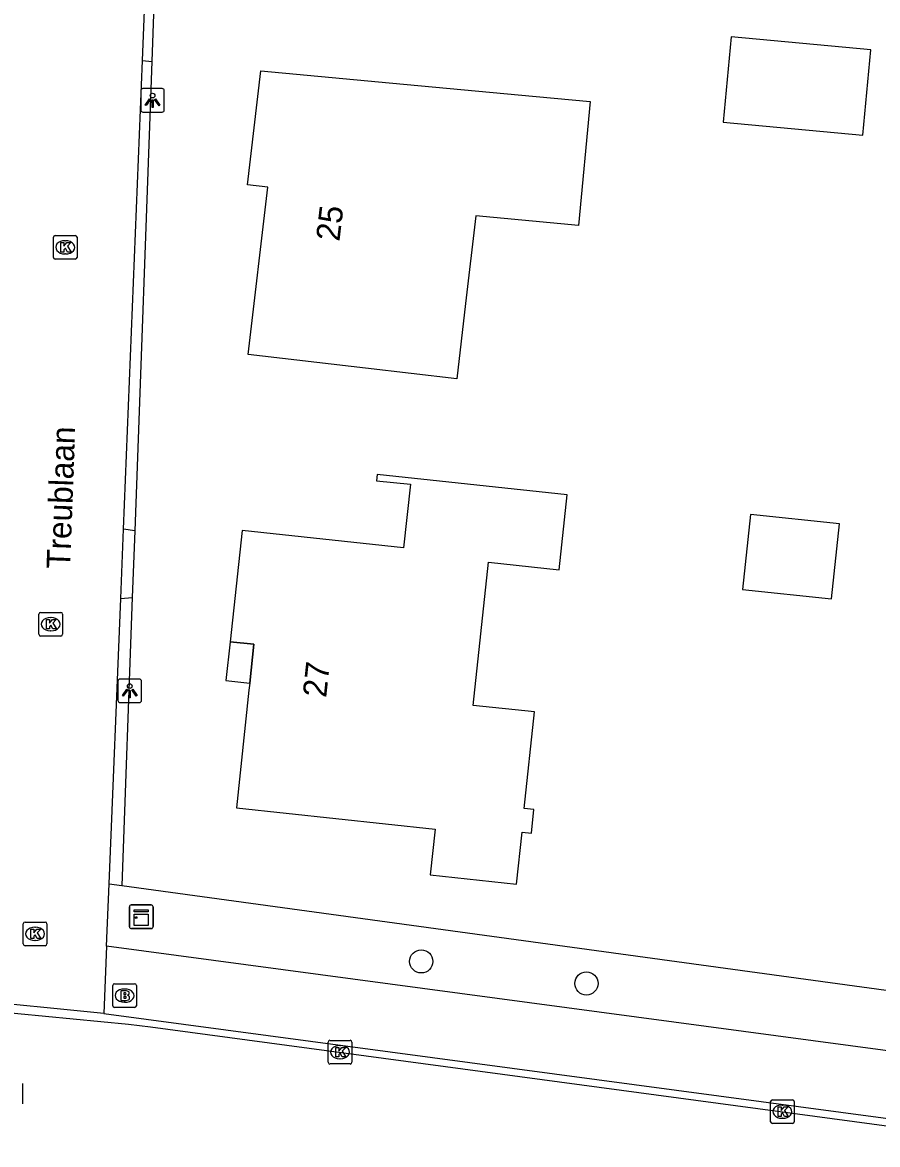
# Model space of a CAD drawing. Extents: x 162157 to 163165, y 378998 to 380775.
# Drawn here: x 162453.3 to 162489.44, y 380403.58 to 380451.03 of the extents above; entities that cross this region are included whole.
import ezdxf

# ---------------------------------------------------------------- set-up
doc = ezdxf.new("R2010")
doc.units = 0
for name, color, linetype in [('IMGEO_Berm_groen', 7, 'Continuous'), ('IMGEO_Boom', 7, 'Continuous'), ('IMGEO_Brandkraan', 7, 'Continuous'), ('IMGEO_Groenvoorziening', 7, 'Continuous'), ('IMGEO_Hek', 7, 'Continuous'), ('IMGEO_Kast', 7, 'Continuous'), ('IMGEO_Kolk', 7, 'Continuous'), ('IMGEO_Lichtpunt', 7, 'Continuous'), ('IMGEO_Openbare_ruimte_label', 7, 'Continuous'), ('IMGEO_Pand', 7, 'Continuous'), ('IMGEO_Pand_nummerreeks', 7, 'Continuous'), ('IMGEO_Pand_overbouw', 7, 'Continuous'), ('IMGEO_Rijbaan_lokaal_gesloten', 7, 'Continuous'), ('IMGEO_Rijbaan_lokaal_open', 7, 'Continuous'), ('IMGEO_Rioolput', 7, 'Continuous'), ('IMGEO_Voetpad_open', 7, 'Continuous')]:
    doc.layers.add(name, color=color, linetype=linetype)

msp = doc.modelspace()

# ---------------------------------------------------------------- linework, layer by layer
at = {"layer": 'IMGEO_Berm_groen'}
msp.add_lwpolyline([(162516.59, 380403.964), (162456.855, 380411.97)], dxfattribs=at)
at = {"layer": 'IMGEO_Boom'}
for centre in [(162470.152, 380411.323), (162477.137, 380410.39)]:
    msp.add_circle(centre, 0.489, dxfattribs=at)
at = {"layer": 'IMGEO_Brandkraan'}
for p, q in [((162457.11, 380409.451), (162457.11, 380410.303)), ((162457.185, 380410.377), (162458.037, 380410.377)), ((162457.598, 380410.157), (162457.623, 380410.157)), ((162458.111, 380410.303), (162458.111, 380409.451)), ((162458.037, 380409.377), (162457.185, 380409.377)), ((162457.621, 380409.597), (162457.596, 380409.597))]:
    msp.add_line(p, q, dxfattribs=at)
for points in [[(162457.11, 380409.451), (162457.11, 380410.303)], [(162457.185, 380410.377), (162458.037, 380410.377)], [(162458.111, 380410.303), (162458.111, 380409.451)], [(162457.458, 380410.077), (162457.458, 380409.677), (162457.671, 380409.677)], [(162457.689, 380410.077), (162457.458, 380410.077)], [(162457.637, 380409.996), (162457.583, 380409.996), (162457.583, 380409.92)], [(162457.583, 380409.92), (162457.636, 380409.92)], [(162457.645, 380409.844), (162457.583, 380409.844), (162457.583, 380409.763)], [(162457.583, 380409.763), (162457.645, 380409.763)], [(162458.037, 380409.377), (162457.185, 380409.377)]]:
    msp.add_lwpolyline(points, dxfattribs=at)
for centre, radius, start, end in [((162457.187, 380410.301), 0.0765, 91.552, 178.448), ((162457.187, 380410.301), 0.0765, 91.552, 178.448), ((162458.035, 380410.301), 0.0765, 1.552, 88.448), ((162458.035, 380410.301), 0.0765, 1.552, 88.448), ((162457.638, 380409.958), 0.0379, 267.8285, 90.9355), ((162457.646, 380409.803), 0.0404, 269.8759, 90.5077), ((162457.677, 380409.928), 0.251, 268.6676, 293.5347), ((162457.693, 380409.932), 0.145, 59.4692, 91.5367), ((162457.718, 380409.979), 0.0922, 285.5137, 58.1501), ((162457.723, 380409.787), 0.105, 301.3115, 78.989), ((162457.187, 380409.453), 0.0765, 181.552, 268.448), ((162457.187, 380409.453), 0.0765, 181.552, 268.448), ((162458.035, 380409.453), 0.0765, 271.552, 358.448), ((162458.035, 380409.453), 0.0765, 271.552, 358.448)]:
    msp.add_arc(centre, radius, start, end, dxfattribs=at)
for centre, major_axis, ratio, start_param, end_param in [((162457.597, 380409.877), (-0.387, 0.002), 0.722429, 4.712389, 7.853982), ((162457.622, 380409.877), (-0.39, 0.002), 0.717154, 1.570796, 4.712389)]:
    msp.add_ellipse(centre, major_axis=major_axis, ratio=ratio, start_param=start_param, end_param=end_param, dxfattribs=at)
at = {"layer": 'IMGEO_Groenvoorziening'}
msp.add_lwpolyline([(162457.497, 380414.534), (162500, 380408.709), (162516.524, 380406.414)], dxfattribs=at)
at = {"layer": 'IMGEO_Hek'}
msp.add_lwpolyline([(162457.497, 380414.534), (162500, 380408.709), (162516.524, 380406.414)], dxfattribs=at)
at = {"layer": 'IMGEO_Kast'}
for p, q in [((162457.818, 380412.786), (162457.818, 380413.627)), ((162457.818, 380413.627), (162457.818, 380412.786)), ((162457.893, 380413.711), (162458.734, 380413.711)), ((162458.734, 380413.711), (162457.893, 380413.711)), ((162458.818, 380413.636), (162458.818, 380412.795)), ((162458.818, 380412.795), (162458.818, 380413.636)), ((162458.743, 380412.711), (162457.902, 380412.711)), ((162457.902, 380412.711), (162458.743, 380412.711))]:
    msp.add_line(p, q, dxfattribs=at)
for points in [[(162458.013, 380413.501), (162458.613, 380413.501), (162458.613, 380413.416), (162458.013, 380413.416), (162458.013, 380413.501)], [(162458.013, 380413.326), (162458.613, 380413.326), (162458.613, 380412.837), (162458.013, 380412.837), (162458.013, 380413.326)]]:
    msp.add_lwpolyline(points, dxfattribs=at)
msp.add_circle((162458.097, 380413.175), 0.0377, dxfattribs=at)
for centre, start, end in [((162457.896, 380413.633), 92.4484, 184.2845), ((162457.896, 380413.633), 92.4484, 184.2845), ((162458.74, 380413.633), 2.4484, 94.2845), ((162458.74, 380413.633), 2.4484, 94.2845), ((162457.896, 380412.789), 182.4484, 274.2845), ((162457.896, 380412.789), 182.4484, 274.2845), ((162458.74, 380412.789), 272.4484, 4.2845), ((162458.74, 380412.789), 272.4484, 4.2845)]:
    msp.add_arc(centre, 0.0779, start, end, dxfattribs=at)
at = {"layer": 'IMGEO_Kolk'}
for p, q in [((162454.603, 380441.092), (162454.603, 380441.944)), ((162454.678, 380442.018), (162455.53, 380442.018)), ((162455.604, 380441.944), (162455.604, 380441.092)), ((162455.091, 380441.798), (162455.116, 380441.798)), ((162455.53, 380441.018), (162454.678, 380441.018)), ((162455.114, 380441.238), (162455.089, 380441.238)), ((162453.989, 380425.154), (162453.989, 380426.006)), ((162454.064, 380426.08), (162454.916, 380426.08)), ((162454.477, 380425.86), (162454.502, 380425.86)), ((162454.99, 380426.006), (162454.99, 380425.154)), ((162454.916, 380425.08), (162454.064, 380425.08)), ((162454.5, 380425.3), (162454.475, 380425.3)), ((162453.406, 380412.988), (162454.258, 380412.988)), ((162453.331, 380412.062), (162453.331, 380412.914)), ((162453.819, 380412.768), (162453.844, 380412.768)), ((162454.332, 380412.914), (162454.332, 380412.062)), ((162453.842, 380412.208), (162453.817, 380412.208)), ((162454.258, 380411.988), (162453.406, 380411.988)), ((162466.221, 380407.06), (162466.221, 380407.912)), ((162466.296, 380407.986), (162467.148, 380407.986)), ((162467.222, 380407.912), (162467.222, 380407.06)), ((162466.709, 380407.766), (162466.734, 380407.766)), ((162467.148, 380406.986), (162466.296, 380406.986)), ((162466.732, 380407.206), (162466.707, 380407.206)), ((162484.919, 380404.544), (162484.919, 380405.396)), ((162484.994, 380405.47), (162485.846, 380405.47)), ((162485.92, 380405.396), (162485.92, 380404.544)), ((162485.407, 380405.25), (162485.432, 380405.25)), ((162485.846, 380404.47), (162484.994, 380404.47)), ((162485.43, 380404.69), (162485.405, 380404.69))]:
    msp.add_line(p, q, dxfattribs=at)
for points in [[(162454.603, 380441.092), (162454.603, 380441.944)], [(162454.678, 380442.018), (162455.53, 380442.018)], [(162455.604, 380441.944), (162455.604, 380441.092)], [(162454.924, 380441.718), (162455.047, 380441.718), (162455.047, 380441.567), (162455.177, 380441.718), (162455.341, 380441.718), (162455.195, 380441.567), (162455.348, 380441.318), (162455.196, 380441.318), (162455.111, 380441.482), (162455.047, 380441.415), (162455.047, 380441.318), (162454.924, 380441.318), (162454.924, 380441.718)], [(162455.53, 380441.018), (162454.678, 380441.018)], [(162453.989, 380425.154), (162453.989, 380426.006)], [(162454.064, 380426.08), (162454.916, 380426.08)], [(162454.99, 380426.006), (162454.99, 380425.154)], [(162454.31, 380425.78), (162454.433, 380425.78), (162454.433, 380425.629), (162454.563, 380425.78), (162454.727, 380425.78), (162454.581, 380425.629), (162454.734, 380425.38), (162454.582, 380425.38), (162454.497, 380425.544), (162454.433, 380425.477), (162454.433, 380425.38), (162454.31, 380425.38), (162454.31, 380425.78)], [(162454.916, 380425.08), (162454.064, 380425.08)], [(162453.406, 380412.988), (162454.258, 380412.988)], [(162453.331, 380412.062), (162453.331, 380412.914)], [(162453.652, 380412.688), (162453.775, 380412.688), (162453.775, 380412.537), (162453.905, 380412.688), (162454.069, 380412.688), (162453.923, 380412.537), (162454.076, 380412.288), (162453.924, 380412.288), (162453.839, 380412.452), (162453.775, 380412.385), (162453.775, 380412.288), (162453.652, 380412.288), (162453.652, 380412.688)], [(162454.332, 380412.914), (162454.332, 380412.062)], [(162454.258, 380411.988), (162453.406, 380411.988)], [(162466.221, 380407.06), (162466.221, 380407.912)], [(162466.296, 380407.986), (162467.148, 380407.986)], [(162467.222, 380407.912), (162467.222, 380407.06)], [(162466.542, 380407.686), (162466.665, 380407.686), (162466.665, 380407.535), (162466.795, 380407.686), (162466.959, 380407.686), (162466.813, 380407.535), (162466.966, 380407.286), (162466.814, 380407.286), (162466.729, 380407.45), (162466.665, 380407.383), (162466.665, 380407.286), (162466.542, 380407.286), (162466.542, 380407.686)], [(162467.148, 380406.986), (162466.296, 380406.986)], [(162484.919, 380404.544), (162484.919, 380405.396)], [(162484.994, 380405.47), (162485.846, 380405.47)], [(162485.92, 380405.396), (162485.92, 380404.544)], [(162485.24, 380405.17), (162485.363, 380405.17), (162485.363, 380405.019), (162485.493, 380405.17), (162485.657, 380405.17), (162485.511, 380405.019), (162485.664, 380404.77), (162485.512, 380404.77), (162485.427, 380404.934), (162485.363, 380404.867), (162485.363, 380404.77), (162485.24, 380404.77), (162485.24, 380405.17)], [(162485.846, 380404.47), (162484.994, 380404.47)]]:
    msp.add_lwpolyline(points, dxfattribs=at)
for centre, start, end in [((162454.68, 380441.942), 91.552, 178.448), ((162454.68, 380441.942), 91.552, 178.448), ((162455.528, 380441.942), 1.552, 88.448), ((162455.528, 380441.942), 1.552, 88.448), ((162454.68, 380441.094), 181.552, 268.448), ((162454.68, 380441.094), 181.552, 268.448), ((162455.528, 380441.094), 271.552, 358.448), ((162455.528, 380441.094), 271.552, 358.448), ((162454.066, 380426.004), 91.552, 178.448), ((162454.066, 380426.004), 91.552, 178.448), ((162454.914, 380426.004), 1.552, 88.448), ((162454.914, 380426.004), 1.552, 88.448), ((162454.066, 380425.156), 181.552, 268.448), ((162454.066, 380425.156), 181.552, 268.448), ((162454.914, 380425.156), 271.552, 358.448), ((162454.914, 380425.156), 271.552, 358.448), ((162453.408, 380412.912), 91.552, 178.448), ((162453.408, 380412.912), 91.552, 178.448), ((162454.256, 380412.912), 1.552, 88.448), ((162454.256, 380412.912), 1.552, 88.448), ((162453.408, 380412.064), 181.552, 268.448), ((162453.408, 380412.064), 181.552, 268.448), ((162454.256, 380412.064), 271.552, 358.448), ((162454.256, 380412.064), 271.552, 358.448), ((162466.298, 380407.91), 91.552, 178.448), ((162466.298, 380407.91), 91.552, 178.448), ((162467.146, 380407.91), 1.552, 88.448), ((162467.146, 380407.91), 1.552, 88.448), ((162466.298, 380407.062), 181.552, 268.448), ((162466.298, 380407.062), 181.552, 268.448), ((162467.146, 380407.062), 271.552, 358.448), ((162467.146, 380407.062), 271.552, 358.448), ((162484.996, 380405.394), 91.552, 178.448), ((162484.996, 380405.394), 91.552, 178.448), ((162485.844, 380405.394), 1.552, 88.448), ((162485.844, 380405.394), 1.552, 88.448), ((162484.996, 380404.546), 181.552, 268.448), ((162484.996, 380404.546), 181.552, 268.448), ((162485.844, 380404.546), 271.552, 358.448), ((162485.844, 380404.546), 271.552, 358.448)]:
    msp.add_arc(centre, 0.0765, start, end, dxfattribs=at)
for centre, major_axis, ratio, start_param, end_param in [((162455.09, 380441.518), (-0.387, 0.002), 0.722429, 4.712389, 7.853982), ((162455.115, 380441.518), (-0.39, 0.002), 0.717154, 1.570796, 4.712389), ((162454.476, 380425.58), (-0.387, 0.002), 0.722429, 4.712389, 7.853982), ((162454.501, 380425.58), (-0.39, 0.002), 0.717154, 1.570796, 4.712389), ((162453.818, 380412.488), (-0.387, 0.002), 0.722429, 4.712389, 7.853982), ((162453.843, 380412.488), (-0.39, 0.002), 0.717154, 1.570796, 4.712389), ((162466.708, 380407.486), (-0.387, 0.002), 0.722429, 4.712389, 7.853982), ((162466.733, 380407.486), (-0.39, 0.002), 0.717154, 1.570796, 4.712389), ((162485.406, 380404.97), (-0.387, 0.002), 0.722429, 4.712389, 7.853982), ((162485.431, 380404.97), (-0.39, 0.002), 0.717154, 1.570796, 4.712389)]:
    msp.add_ellipse(centre, major_axis=major_axis, ratio=ratio, start_param=start_param, end_param=end_param, dxfattribs=at)
at = {"layer": 'IMGEO_Lichtpunt'}
for p, q in [((162458.296, 380448.135), (162458.296, 380447.328)), ((162458.296, 380448.135), (162458.296, 380447.328)), ((162459.198, 380448.23), (162458.39, 380448.23)), ((162459.198, 380448.23), (162458.39, 380448.23)), ((162459.292, 380447.328), (162459.292, 380448.135)), ((162459.292, 380447.328), (162459.292, 380448.135)), ((162458.39, 380447.234), (162459.198, 380447.234)), ((162458.39, 380447.234), (162459.198, 380447.234)), ((162457.332, 380423.169), (162457.332, 380422.362)), ((162457.332, 380423.169), (162457.332, 380422.362)), ((162458.234, 380423.264), (162457.426, 380423.264)), ((162458.234, 380423.264), (162457.426, 380423.264)), ((162458.328, 380422.362), (162458.328, 380423.169)), ((162458.328, 380422.362), (162458.328, 380423.169)), ((162457.426, 380422.268), (162458.234, 380422.268)), ((162457.426, 380422.268), (162458.234, 380422.268))]:
    msp.add_line(p, q, dxfattribs=at)
for points in [[(162458.67, 380447.799), (162458.709, 380447.771), (162458.521, 380447.509), (162458.483, 380447.536), (162458.67, 380447.799)], [(162458.772, 380447.751), (162458.819, 380447.751), (162458.819, 380447.429), (162458.772, 380447.429), (162458.772, 380447.751)], [(162458.882, 380447.771), (162458.92, 380447.798), (162459.107, 380447.536), (162459.068, 380447.508), (162458.882, 380447.771)], [(162457.706, 380422.833), (162457.745, 380422.805), (162457.557, 380422.543), (162457.519, 380422.57), (162457.706, 380422.833)], [(162457.808, 380422.785), (162457.855, 380422.785), (162457.855, 380422.463), (162457.808, 380422.463), (162457.808, 380422.785)], [(162457.918, 380422.805), (162457.956, 380422.832), (162458.143, 380422.57), (162458.104, 380422.542), (162457.918, 380422.805)]]:
    msp.add_lwpolyline(points, dxfattribs=at)
for centre in [(162458.795, 380447.933), (162457.831, 380422.967)]:
    msp.add_circle(centre, 0.0994, dxfattribs=at)
for centre, start, end in [((162458.39, 380448.135), 90, 180), ((162458.39, 380448.135), 90, 180), ((162459.198, 380448.135), 0, 90), ((162459.198, 380448.135), 0, 90), ((162458.39, 380447.328), 180, 270), ((162458.39, 380447.328), 180, 270), ((162459.198, 380447.328), 270, 0), ((162459.198, 380447.328), 270, 360), ((162457.426, 380423.169), 90, 180), ((162457.426, 380423.169), 90, 180), ((162458.234, 380423.169), 0, 90), ((162458.234, 380423.169), 0, 90), ((162457.426, 380422.362), 180, 270), ((162457.426, 380422.362), 180, 270), ((162458.234, 380422.362), 270, 0), ((162458.234, 380422.362), 270, 360)]:
    msp.add_arc(centre, 0.0946, start, end, dxfattribs=at)
at = {"layer": 'IMGEO_Pand'}
for points in [[(162489.16, 380449.876), (162483.251, 380450.426), (162482.915, 380446.817), (162488.824, 380446.268), (162489.16, 380449.876)], [(162476.804, 380442.448), (162472.461, 380442.852), (162472.028, 380439.141), (162471.657, 380435.961), (162467.803, 380436.411), (162462.836, 380436.992), (162463.662, 380444.064), (162462.808, 380444.164), (162463.371, 380448.982), (162468.35, 380448.52), (162474.245, 380447.972), (162477.291, 380447.689), (162476.804, 380442.448)], [(162472.995, 380428.2), (162475.986, 380427.88), (162476.325, 380431.051), (162468.294, 380431.908), (162468.266, 380431.65), (162469.695, 380431.497), (162469.408, 380428.813), (162462.578, 380429.542), (162462.075, 380424.841), (162463.078, 380424.734), (162462.903, 380423.093), (162462.871, 380422.793), (162462.339, 380417.816), (162470.74, 380416.918), (162470.533, 380414.979), (162474.177, 380414.59), (162474.413, 380416.793), (162474.81, 380416.75), (162474.917, 380417.744), (162474.504, 380417.789), (162474.94, 380421.871), (162472.348, 380422.148), (162472.995, 380428.2)], [(162484.071, 380430.223), (162483.732, 380427.053), (162487.491, 380426.651), (162487.83, 380429.822), (162484.071, 380430.223)]]:
    msp.add_lwpolyline(points, dxfattribs=at)
at = {"layer": 'IMGEO_Pand_overbouw'}
msp.add_lwpolyline([(162462.075, 380424.841), (162461.899, 380423.2), (162462.903, 380423.093), (162463.078, 380424.734)], close=True, dxfattribs=at)
at = {"layer": 'IMGEO_Rijbaan_lokaal_gesloten'}
for points in [[(162456.74, 380409.122), (162450.786, 380409.707)], [(162450.751, 380409.341), (162457.772, 380408.665), (162458.711, 380408.563), (162500, 380403.006), (162522.1, 380400.031)], [(162456.74, 380409.122), (162500, 380403.326), (162514.74, 380401.351)]]:
    msp.add_lwpolyline(points, dxfattribs=at)
at = {"layer": 'IMGEO_Rijbaan_lokaal_open'}
for points in [[(162458.371, 380449.424), (162458.629, 380455.789)], [(162457.569, 380429.598), (162458.371, 380449.424)], [(162458.762, 380449.371), (162458.041, 380429.529)], [(162458.371, 380449.424), (162458.762, 380449.371)], [(162457.45, 380426.663), (162457.569, 380429.598)], [(162458.041, 380429.529), (162457.569, 380429.598)], [(162456.962, 380414.607), (162457.45, 380426.663)], [(162457.45, 380426.663), (162457.939, 380426.708)], [(162457.939, 380426.708), (162457.497, 380414.534)], [(162456.855, 380411.97), (162456.962, 380414.607)], [(162456.962, 380414.607), (162457.497, 380414.534)], [(162456.855, 380411.97), (162456.74, 380409.122)]]:
    msp.add_lwpolyline(points, dxfattribs=at)
at = {"layer": 'IMGEO_Rioolput'}
msp.add_line((162453.295, 380406.16), (162453.295, 380405.308), dxfattribs=at)
msp.add_lwpolyline([(162453.295, 380406.16), (162453.295, 380405.308)], dxfattribs=at)
at = {"layer": 'IMGEO_Voetpad_open'}
for points in [[(162458.629, 380455.789), (162458.995, 380455.79), (162458.762, 380449.371)], [(162458.041, 380429.529), (162457.939, 380426.708)]]:
    msp.add_lwpolyline(points, dxfattribs=at)

# ---------------------------------------------------------------- texts
at = {"layer": 'IMGEO_Openbare_ruimte_label'}
msp.add_text('Treublaan', height=1, rotation=87.9362, dxfattribs=at).set_placement((162455.31, 380427.909))
at = {"layer": 'IMGEO_Pand_nummerreeks'}
for s, rotation, p in [('25', 83.3367, (162466.694, 380441.746)), ('27', 83.9039, (162466.133, 380422.454))]:
    msp.add_text(s, height=1, rotation=rotation, dxfattribs=at).set_placement(p)

doc.saveas('drawing.dxf')
